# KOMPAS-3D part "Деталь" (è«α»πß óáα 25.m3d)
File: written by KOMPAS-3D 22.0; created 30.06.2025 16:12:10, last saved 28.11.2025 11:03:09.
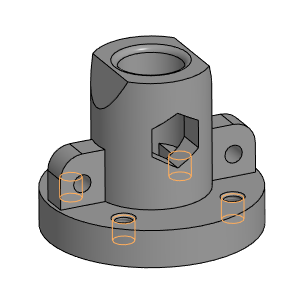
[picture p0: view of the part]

Document properties: Автор: alymovy@yandex.ru; Организация: HP; Полное имя файла: Корпус вар 25.cdw

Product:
- Part/product: Деталь
    Материал: Фторопласт-4 ГОСТ 10007-80 Е (density 2200 kg/m3)
    Масса: 1.340345
    Форматы листов документа: A3

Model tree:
1. Эскиз:1
2. Элемент выдавливания:1
     Расстояние 1 = 25
3. Эскиз:2  (with: Элемент выдавливания:1)
4. Элемент выдавливания:2
     Расстояние 1 = 85
5. Эскиз:3  (with: Элемент выдавливания:1)
6. Ребро жесткости:1
     Толщина стенки 1 = 18; Толщина стенки 2 = 1
7. Зеркальный массив:1
8. Экземпляр ( 1 )
9. Экземпляр ( 2 )  (with: Ребро жесткости:1)
10. Эскиз:4
11. Элемент выдавливания:3
     Расстояние 1 = 70
12. Эскиз:5  (with: Элемент выдавливания:2)
13. Элемент выдавливания:4
     Расстояние 2 = 65
14. Эскиз:6  (with: Элемент выдавливания:4)
15. Элемент выдавливания:5
     Расстояние 2 = 45
16. Эскиз:7  (with: Ребро жесткости:1, Элемент выдавливания:1)
17. Элемент выдавливания:6
18. Эскиз:8  (with: Элемент выдавливания:2)
19. Элемент выдавливания:7
     Расстояние 1 = 70
20. Скругление:1  (with: Элемент выдавливания:4)
     Радиус = 4
21. Эскиз:9  (with: Элемент выдавливания:1, Элемент выдавливания:2)
22. Отверстие:1  (with: Элемент выдавливания:1, Ребро жесткости:1)  (labels: M14)
     Глубина выреза = 20; Диаметр отверстия = 11.8349; Угол конуса дна = 118; Расстояние 1 = -28.4767; Расстояние 2 = 29.5233; Диаметр зенковки = 15.8349; Глубина зенковки = 2; Угол зенковки = 90
23. M14  (labels: cil0_24705-2004 coarse)
     Длина резьбы = 15; Шаг резьбы = 2; Номинальный диаметр резьбы = 14
24. Зеркальный массив:2  (with: Экземпляр ( 1 ), Экземпляр ( 2 ), Отверстие:1)
25. Зеркальный массив:3  (with: Экземпляр ( 1 ), Экземпляр ( 2 ), Зеркальный массив:2, Отверстие:1)
26. Экземпляр ( 2 )  (with: Отверстие:1)

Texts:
  Линейный размер с обрывом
